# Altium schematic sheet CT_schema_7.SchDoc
size 274 x 160 mm
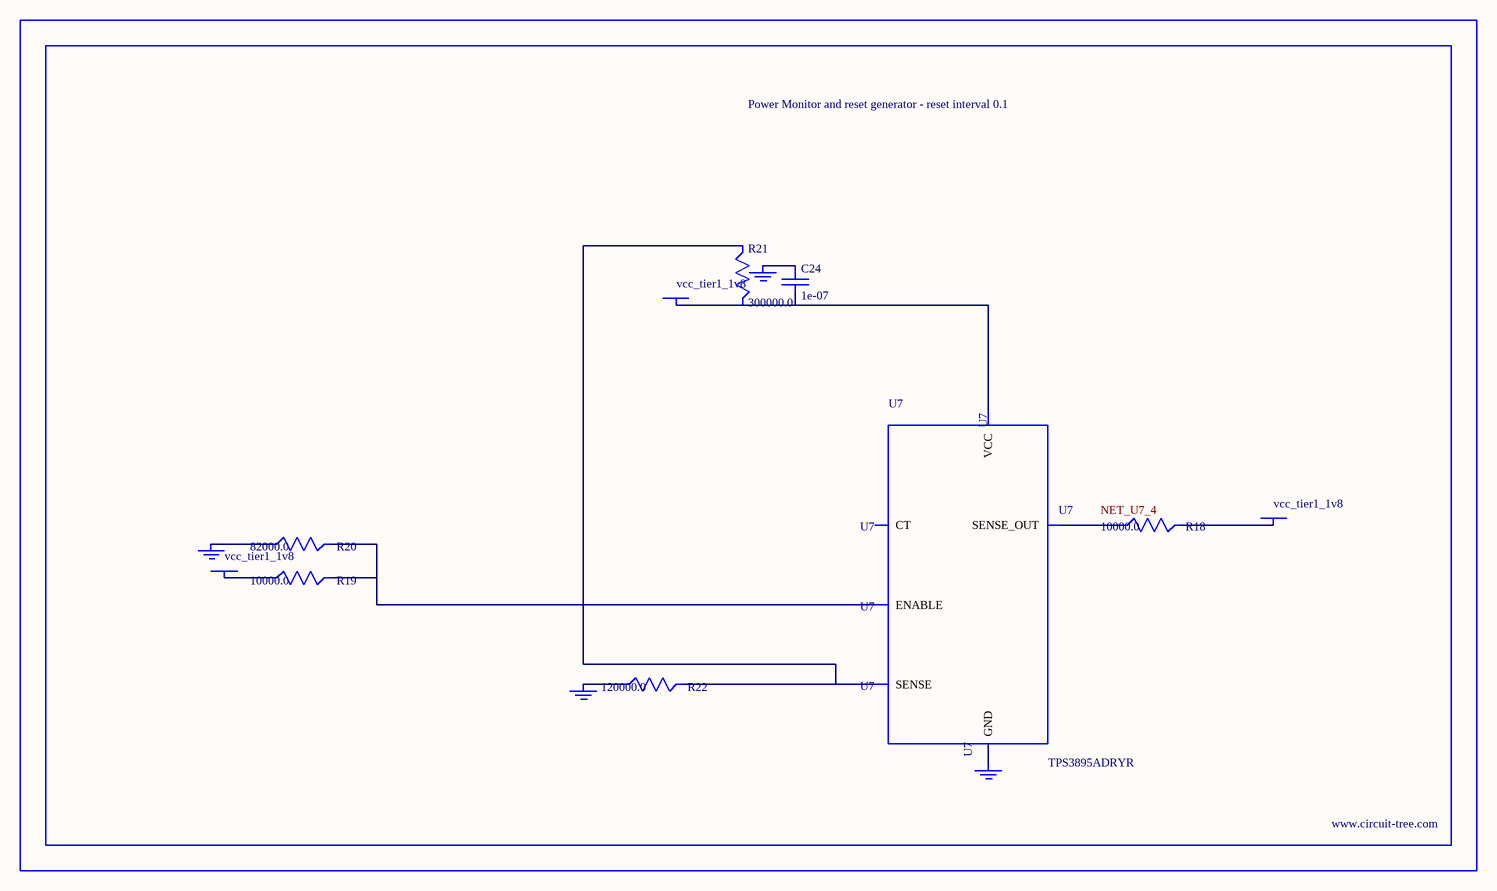
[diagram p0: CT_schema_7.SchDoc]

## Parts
BORDER6  (no value)
C24  1e-07  [C0402]
GND_INSTANCE_6_0  (no value)
GND_INSTANCE_6_1  (no value)
GND_INSTANCE_6_2  (no value)
GND_INSTANCE_6_3  (no value)
POWER_INSTANCE_6_0  vcc_tier1_1v8
POWER_INSTANCE_6_1  vcc_tier1_1v8
POWER_INSTANCE_6_2  vcc_tier1_1v8
R18  10000.0  [R0603]
R19  10000.0  [R0603]
R20  82000.0  [R0603]
R21  300000.0  [R0603]
R22  120000.0  [R0603]
U7  TPS3895ADRYR  [SON-6]

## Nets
NetC24_1: C24.1 GND_INSTANCE_6_2.0(GND)
NetC24_2: C24.2 POWER_INSTANCE_6_2.0(PWR) R21.2 U7.6(VCC)
NetGND_INSTANCE_6_0_0: GND_INSTANCE_6_0.0(GND) R20.1
NetGND_INSTANCE_6_1_0: GND_INSTANCE_6_1.0(GND) R22.1
NetGND_INSTANCE_6_3_0: GND_INSTANCE_6_3.0(GND) U7.2(GND)
NetPOWER_INSTANCE_6_0_0: POWER_INSTANCE_6_0.0(PWR) R19.1
NetPOWER_INSTANCE_6_1_0: POWER_INSTANCE_6_1.0(PWR) R18.2
NetR18_1: R18.1 U7.4(SENSE_OUT)
NetR19_2: R19.2 R20.2 U7.1(ENABLE)
NetR21_1: R21.1 R22.2 U7.3(SENSE)

Not connected (* = marked no-connect by the designer): U7 5(CT)

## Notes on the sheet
- Labels drawn without touching a wire or pin: NET_U7_4

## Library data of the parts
BORDER6 = BORDER_PAGE6
C24 = C0402C104K3RACTU
GND_INSTANCE_6_0-GND_INSTANCE_6_3 = GND
POWER_INSTANCE_6_0-POWER_INSTANCE_6_2 = PWR
R18 R19 = RC0603JR-0710KL
R20 = RC0603JR-0782KL
R21 = RC0603JR-07300KL
R22 = RC0603JR-07120KL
